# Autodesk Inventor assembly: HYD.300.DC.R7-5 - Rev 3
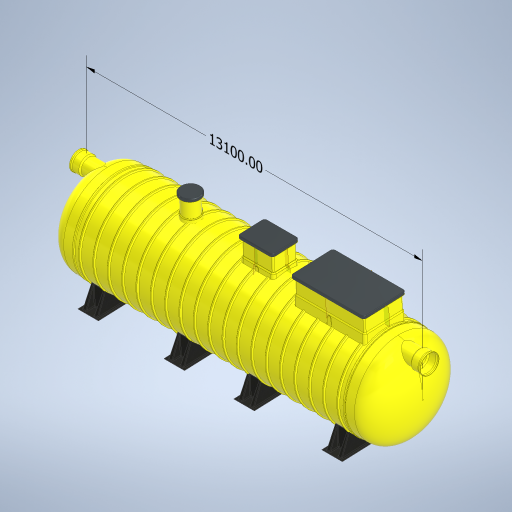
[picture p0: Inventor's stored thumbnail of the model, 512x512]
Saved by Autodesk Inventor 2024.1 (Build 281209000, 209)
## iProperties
Created: 2023-08
Part Number: HYD.300.DC.R7-5 - Rev 3
Document SubType Name: Assembly
Designer: macga
Author: macga
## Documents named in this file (47)
- D:\$ Protector Vault\Workspace\Automation Files\1. Protector Stardard Products\HydroProtectors\FAMILY\HYD.300 - Vernon\HYD.300.DC.R7-5 - Rev 3.iam
- D:\$ Protector Vault\Workspace\1. Protector Stardard Products\HydroProtectors\FAMILY\HORIZONTAL TANK - IPART\HORIZONTAL TANK - IPART.ipt
- D:\$ Protector Vault\Workspace\1. Protector Stardard Products\HydroProtectors\FAMILY\DOME - IPART\DOME - IPART.ipt
- D:\$ Protector Vault\Workspace\1. Protector Stardard Products\HydroProtectors\FAMILY\FOOT - IPART\FRP Foot - IPART.ipt
- D:\$ Protector Vault\Workspace\1. Protector Stardard Products\HydroProtectors\FAMILY\ACDTUBE - IPART\ACDTUBE - IPART.ipt
- D:\$ Protector Vault\Workspace\1. Protector Stardard Products\HydroProtectors\FAMILY\ACD FLOAT VALVE - IPART\ACD.FloatValve - IASSY.iam
- D:\$ Protector Vault\Workspace\1. Protector Stardard Products\HydroProtectors\FAMILY\OUTLET ELBOW - IPART\OUTLET ELBOW - IPART.ipt
- D:\$ Protector Vault\Workspace\1. Protector Stardard Products\HydroProtectors\Coalescer Guide Rail.ipt
- D:\$ Protector Vault\Workspace\1. Protector Stardard Products\HydroProtectors\Upper Guide Rai Braket.ipt
- D:\$ Protector Vault\Workspace\1. Protector Stardard Products\Standard Components\Flanged Vent.ipt
- D:\$ Protector Vault\Workspace\1. Protector Stardard Products\Xtremeprotector\Vault\Chain.ipt
- D:\$ Protector Vault\Workspace\1. Protector Stardard Products\Xtremeprotector\Vault\Lifting Eye.ipt
- D:\$ Protector Vault\Workspace\1. Protector Stardard Products\HydroProtectors\FAMILY\ACDTUBE - IPART\ACDTUBE - IPART\ACDTUBE.750-3300.ipt
- D:\$ Protector Vault\Workspace\1. Protector Stardard Products\HydroProtectors\FAMILY\ACD FLOAT VALVE - IPART\ACD.FloatValve - IASSY\ACD.FVALVE.750.ASSY.iam
- D:\$ Protector Vault\Workspace\1. Protector Stardard Products\HydroProtectors\FAMILY\SU.900X1200.ManwayRiserAdaptor - IPART\SU.900X1200.ManwayRiserAdapator - IPART.ipt
- D:\$ Protector Vault\Workspace\1. Protector Stardard Products\Standard Components\900x1200x600 Manway Riser.ipt
- D:\$ Protector Vault\Workspace\1. Protector Stardard Products\Standard Components\900x1200 Manway Cover ST\900x900 Manway Cover Class D ST-02.ipt
- D:\$ Protector Vault\Workspace\1. Protector Stardard Products\Standard Components\900x1200 Manway Cover ST.ipt
- D:\$ Protector Vault\Workspace\1. Protector Stardard Products\HydroProtectors\FAMILY\DOME - IPART\DOME - IPART\SU.DOME.3500-22.ipt
- D:\$ Protector Vault\Workspace\1. Protector Stardard Products\HydroProtectors\FAMILY\FOOT - IPART\FRP Foot - IPART\SU.HS.FOOT.3500.ipt
- D:\$ Protector Vault\Workspace\1. Protector Stardard Products\HydroProtectors\FAMILY\HYD.BAFFLE - IPART\SU.BAFFLE.3500\SU.BAFFLE.3500-1100x775x610.ipt
- D:\$ Protector Vault\Workspace\1. Protector Stardard Products\HydroProtectors\FAMILY\HYD.BAFFLE - IPART\SU.BAFFLE.3500.ipt
- D:\$ Protector Vault\Workspace\1. Protector Stardard Products\HydroProtectors\FAMILY\ACD Base - IPART\SU.ACDBASE.3500\SU.ACDBASE.3500-700,1100.ipt
- D:\$ Protector Vault\Workspace\1. Protector Stardard Products\HydroProtectors\FAMILY\ACD Base - IPART\SU.ACDBASE.3500.ipt
- D:\$ Protector Vault\Workspace\1. Protector Stardard Products\HydroProtectors\FAMILY\SU.900X1200.ManwayRiserAdaptor - IPART\SU.900X1200.ManwayRiserAdapator - IPART\SU.900x1200ManwayRiserAdapter.3500.ipt
- D:\$ Protector Vault\Workspace\1. Protector Stardard Products\HydroProtectors\FAMILY\Coalescer Guide Rail-0124.ipt
- D:\$ Protector Vault\Workspace\1. Protector Stardard Products\HydroProtectors\FAMILY\Coalescer Guide Rail-0125.ipt
- D:\$ Protector Vault\Workspace\1. Protector Stardard Products\HydroProtectors\FAMILY\CF.BASE - IPART\CF BASE PENTA  2.0 - IPART.ipt
- D:\$ Protector Vault\Workspace\1. Protector Stardard Products\Standard Components\1500x2700 Manway Adaptor\SU.1500x2700ManwayRiserAdaptor.3500.ipt
- D:\$ Protector Vault\Workspace\1. Protector Stardard Products\Standard Components\1500x2700 Manway Adaptor.ipt
- D:\$ Protector Vault\Workspace\1. Protector Stardard Products\Standard Components\1500x2700x600 Manway Riser.ipt
- D:\$ Protector Vault\Workspace\1. Protector Stardard Products\Standard Components\1500x2700 Manway Cover ST\1500x2700 Manway Cover Class D ST-02.ipt
- D:\$ Protector Vault\Workspace\1. Protector Stardard Products\Standard Components\1500x2700 Manway Cover ST.ipt
- D:\$ Protector Vault\Workspace\1. Protector Stardard Products\HydroProtectors\FAMILY\HORIZONTAL TANK - IPART\HORIZONTAL TANK - IPART\WIN.HB.3500x10600L-22.ipt
- D:\$ Protector Vault\Workspace\1. Protector Stardard Products\HydroProtectors\FAMILY\COALESCER FILTER - IPART\CF-R7.iam
- D:\$ Protector Vault\Workspace\1. Protector Stardard Products\Xtremeprotector\Vault\Chain\Chain-55.ipt
- D:\$ Protector Vault\Workspace\1. Protector Stardard Products\HydroProtectors\FAMILY\CF.BASE - IPART\CF BASE PENTA  2.0 - IPART\SU.CFBASE.3500.B2.5-R7-OP.450.ipt
- D:\$ Protector Vault\Workspace\1. Protector Stardard Products\HydroProtectors\FAMILY\COALESCER FILTER - IPART\CF-R7_MIR6.iam
- D:\$ Protector Vault\Workspace\1. Protector Stardard Products\Xtremeprotector\Vault\Lifting Eye_MIR12.ipt
- D:\$ Protector Vault\Workspace\1. Protector Stardard Products\HydroProtectors\Upper Guide Rai Braket_MIR12.ipt
- D:\$ Protector Vault\Workspace\1. Protector Stardard Products\600 Dia Adaptor, Riser, Cover Assy - 3500\600 Dia Adaptor, Riser, Class D Cover Assy -3000.iam
- D:\$ Protector Vault\Workspace\1. Protector Stardard Products\600 Dia Adaptor, Riser, Cover Assy - 3500.iam
- D:\$ Protector Vault\Workspace\1. Protector Stardard Products\StormProtector\600 Storm Pro Inlet Elbow.ipt
- D:\$ Protector Vault\Workspace\1. Protector Stardard Products\HydroProtectors\FAMILY\OUTLET ELBOW - IPART\OUTLET ELBOW - IPART\OutletPipeElbow.600D-100DCoupling.ipt
- D:\$ Protector Vault\Workspace\1. Protector Stardard Products\StormProtector\600 Storm Pro Pipe and Socket.ipt
- D:\$ Protector Vault\Workspace\1. Protector Stardard Products\StormProtector\ISO 4065 Pipe DN630x15.4xS20 - 3000.ipt
- D:\$ Protector Vault\Workspace\1. Protector Stardard Products\Trade Waste Sampling Point Assembly 600.iam
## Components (51 placed, 30 different names)
1. WIN.HB.3500x10600L-22:1
2. SU.DOME.3500-22:1 — Mate:1, Mate:3, Mate:78, Mate:93, Mate:176, Angle:5, Angle:11
3. 600 Storm Pro Inlet Elbow:1 — Mate:176, Angle:5, Tangent:135
4. SU.DOME.3500-22:2 — Mate:2, Mate:4, Mate:94, Mate:172
5. SU.HS.FOOT.3500:1 — Mate:74, Mate:75, Angle:7
6. SU.HS.FOOT.3500:2 — Mate:76, Mate:77, Angle:10
7. SU.HS.FOOT.3500:3 — Mate:149, Angle:9, Mate:232
8. SU.HS.FOOT.3500:4 — Mate:147, Mate:148, Angle:8
9. SU.BAFFLE.3500-1100x775x610:1
10. SU.ACDBASE.3500-700,1100:1
11. ACDTUBE.750-3300:1 — Mate:14, Mate:208
12. ACD.FVALVE.750.ASSY:1 [sub-assembly] — Mate:208
13. SU.CFBASE.3500.B2.5-R7-OP.450:1 — Mate:16, Flush:173, Mate:154, Mate:221, Mate:222, Mate:223, Mate:247, Mate:248
14. CF-R7:2 [sub-assembly] — Mate:86, Tangent:4
15. CF-R7:1 [sub-assembly] — Mate:154, Mate:157, Tangent:126
16. ISO 4065 Pipe DN630x15.4xS20 - 3000:1 — Mate:247, Mate:248, Mate:251, Mate:252
17. OutletPipeElbow.600D-100DCoupling:2 — Mate:249, Mate:250, Mate:251, Mate:252
18. 600 Storm Pro Pipe and Socket:1 — Mate:249, Mate:250, Mate:253, Mate:254
19. 900x1200x600 Manway Riser:1 — Mate:187, Mate:188, Mate:189
20. 900x900 Manway Cover Class D ST-02:1 — Flush:222
21. Flanged Vent:3 — Mate:194, Mate:195
22. Flanged Vent:4
23. SU.900x1200ManwayRiserAdapter.3500:1
24. Chain-55:1 — Mate:157, Tangent:126, Tangent:127
25. Chain-55:2 — Mate:86, Tangent:4, Tangent:128
26. Lifting Eye:1 — Tangent:127, Mate:160
27. Lifting Eye:2 — Tangent:128, Mate:161
28. Coalescer Guide Rail-0124:1 — Mate:62, Mate:63, Flush:5
29. Coalescer Guide Rail-0125:2 — Mate:64, Mate:65, Flush:6
30. Upper Guide Rai Braket:1 — Mate:62, Mate:63, Flush:5, Mate:160
31. Upper Guide Rai Braket:2 — Mate:64, Mate:65, Flush:6, Mate:161
32. SU.1500x2700ManwayRiserAdaptor.3500:1
33. 1500x2700x600 Manway Riser:1 — Mate:233, Mate:234, Mate:235
34. 1500x2700 Manway Cover Class D ST-02:1 — Angle:17
35. CF-R7:3 [sub-assembly] — Mate:236, Tangent:130
36. Coalescer Guide Rail-0124:5 — Mate:221, Mate:222, Mate:223
37. Upper Guide Rai Braket:3
38. Chain-55:3 — Tangent:129, Mate:236
39. Lifting Eye:3 — Tangent:129, Mate:233, Mate:234, Mate:235, Tangent:130
40. CF-R7_MIR6:1 [sub-assembly] — Tangent:134, Mate:244, Flush:221
41. CF-R7_MIR6:2 [sub-assembly] — Tangent:133, Mate:243, Flush:221
42. Chain-55:4 — Tangent:131, Tangent:133, Mate:243
43. Chain-55:5 — Tangent:132, Tangent:134, Mate:244
44. Lifting Eye_MIR12:1 — Tangent:131, Mate:241
45. Lifting Eye_MIR12:2 — Tangent:132, Mate:242
46. Coalescer Guide Rail-0124:6 — Flush:219, Mate:237, Mate:238
47. Coalescer Guide Rail-0125:7 — Flush:220, Mate:239, Mate:240
48. Upper Guide Rai Braket_MIR12:1 — Flush:219, Mate:237, Mate:238, Mate:241
49. Upper Guide Rai Braket_MIR12:2 — Flush:220, Mate:239, Mate:240, Mate:242
50. 600 Dia Adaptor, Riser, Class D Cover Assy -3000:1 [sub-assembly] — Mate:245, Flush:222, Mate:246
51. Trade Waste Sampling Point Assembly 600:1 [sub-assembly] — Mate:253, Angle:17, Mate:254
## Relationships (84: Mate 59, Tangent 11, Flush 7, Angle 7)
- Mate:1: SU.DOME.3500-22:1
- Mate:2: SU.DOME.3500-22:2
- Mate:3: SU.DOME.3500-22:1
- Mate:4: SU.DOME.3500-22:2
- Mate:14: ACDTUBE.750-3300:1
- Mate:16: SU.CFBASE.3500.B2.5-R7-OP.450:1
- Flush:173: SU.CFBASE.3500.B2.5-R7-OP.450:1
- Mate:62: Coalescer Guide Rail-0124:1 ↔ Upper Guide Rai Braket:1
- Mate:63: Coalescer Guide Rail-0124:1 ↔ Upper Guide Rai Braket:1
- Flush:5: Coalescer Guide Rail-0124:1 ↔ Upper Guide Rai Braket:1
- Mate:64: Coalescer Guide Rail-0125:2 ↔ Upper Guide Rai Braket:2
- Mate:65: Coalescer Guide Rail-0125:2 ↔ Upper Guide Rai Braket:2
- Flush:6: Coalescer Guide Rail-0125:2 ↔ Upper Guide Rai Braket:2
- Mate:74: SU.HS.FOOT.3500:1
- Mate:75: SU.HS.FOOT.3500:1
- Mate:76: SU.HS.FOOT.3500:2
- Mate:77: SU.HS.FOOT.3500:2
- Mate:78: SU.DOME.3500-22:1
- Mate:86: CF-R7:2 ↔ Chain-55:2
- Tangent:4: CF-R7:2 ↔ Chain-55:2
- Mate:93: SU.DOME.3500-22:1
- Mate:94: SU.DOME.3500-22:2
- Mate:208: ACDTUBE.750-3300:1 ↔ ACD.FVALVE.750.ASSY:1
- Mate:147: SU.HS.FOOT.3500:4
- Mate:148: SU.HS.FOOT.3500:4
- Mate:149: SU.HS.FOOT.3500:3
- Mate:176: SU.DOME.3500-22:1 ↔ 600 Storm Pro Inlet Elbow:1
- Angle:5: SU.DOME.3500-22:1 ↔ 600 Storm Pro Inlet Elbow:1
- Angle:7: SU.HS.FOOT.3500:1
- Angle:8: SU.HS.FOOT.3500:4
- Angle:9: SU.HS.FOOT.3500:3
- Angle:10: SU.HS.FOOT.3500:2
- Angle:11: SU.DOME.3500-22:1
- Mate:154: SU.CFBASE.3500.B2.5-R7-OP.450:1 ↔ CF-R7:1
- Mate:157: CF-R7:1 ↔ Chain-55:1
- Tangent:126: CF-R7:1 ↔ Chain-55:1
- Tangent:127: Chain-55:1 ↔ Lifting Eye:1
- Tangent:128: Chain-55:2 ↔ Lifting Eye:2
- Mate:160: Lifting Eye:1 ↔ Upper Guide Rai Braket:1
- Mate:161: Lifting Eye:2 ↔ Upper Guide Rai Braket:2
- Mate:172: SU.DOME.3500-22:2
- Mate:187: 900x1200x600 Manway Riser:1
- Mate:188: 900x1200x600 Manway Riser:1
- Mate:189: 900x1200x600 Manway Riser:1
- Mate:194: Flanged Vent:3
- Mate:195: Flanged Vent:3
- Mate:221: SU.CFBASE.3500.B2.5-R7-OP.450:1 ↔ Coalescer Guide Rail-0124:5
- Mate:222: SU.CFBASE.3500.B2.5-R7-OP.450:1 ↔ Coalescer Guide Rail-0124:5
- Mate:223: SU.CFBASE.3500.B2.5-R7-OP.450:1 ↔ Coalescer Guide Rail-0124:5
- Mate:232: SU.HS.FOOT.3500:3
- Tangent:129: Chain-55:3 ↔ Lifting Eye:3
- Mate:233: 1500x2700x600 Manway Riser:1 ↔ Lifting Eye:3
- Mate:234: 1500x2700x600 Manway Riser:1 ↔ Lifting Eye:3
- Mate:235: 1500x2700x600 Manway Riser:1 ↔ Lifting Eye:3
- Mate:236: CF-R7:3 ↔ Chain-55:3
- Tangent:130: CF-R7:3 ↔ Lifting Eye:3
- Flush:219: Coalescer Guide Rail-0124:6 ↔ Upper Guide Rai Braket_MIR12:1
- Mate:237: Coalescer Guide Rail-0124:6 ↔ Upper Guide Rai Braket_MIR12:1
- Mate:238: Coalescer Guide Rail-0124:6 ↔ Upper Guide Rai Braket_MIR12:1
- Flush:220: Coalescer Guide Rail-0125:7 ↔ Upper Guide Rai Braket_MIR12:2
- Mate:239: Coalescer Guide Rail-0125:7 ↔ Upper Guide Rai Braket_MIR12:2
- Mate:240: Coalescer Guide Rail-0125:7 ↔ Upper Guide Rai Braket_MIR12:2
- Tangent:131: Chain-55:4 ↔ Lifting Eye_MIR12:1
- Mate:241: Lifting Eye_MIR12:1 ↔ Upper Guide Rai Braket_MIR12:1
- Tangent:132: Chain-55:5 ↔ Lifting Eye_MIR12:2
- Mate:242: Lifting Eye_MIR12:2 ↔ Upper Guide Rai Braket_MIR12:2
- Tangent:133: CF-R7_MIR6:2 ↔ Chain-55:4
- Mate:243: CF-R7_MIR6:2 ↔ Chain-55:4
- Tangent:134: CF-R7_MIR6:1 ↔ Chain-55:5
- Mate:244: CF-R7_MIR6:1 ↔ Chain-55:5
- Flush:221: CF-R7_MIR6:1 ↔ CF-R7_MIR6:2
- Mate:245: 600 Dia Adaptor, Riser, Class D Cover Assy -3000:1
- Flush:222: 900x900 Manway Cover Class D ST-02:1 ↔ 600 Dia Adaptor, Riser, Class D Cover Assy -3000:1
- Mate:246: 600 Dia Adaptor, Riser, Class D Cover Assy -3000:1
- Mate:247: SU.CFBASE.3500.B2.5-R7-OP.450:1 ↔ ISO 4065 Pipe DN630x15.4xS20 - 3000:1
- Mate:248: SU.CFBASE.3500.B2.5-R7-OP.450:1 ↔ ISO 4065 Pipe DN630x15.4xS20 - 3000:1
- Mate:249: OutletPipeElbow.600D-100DCoupling:2 ↔ 600 Storm Pro Pipe and Socket:1
- Mate:250: OutletPipeElbow.600D-100DCoupling:2 ↔ 600 Storm Pro Pipe and Socket:1
- Mate:251: ISO 4065 Pipe DN630x15.4xS20 - 3000:1 ↔ OutletPipeElbow.600D-100DCoupling:2
- Mate:252: ISO 4065 Pipe DN630x15.4xS20 - 3000:1 ↔ OutletPipeElbow.600D-100DCoupling:2
- Tangent:135: 600 Storm Pro Inlet Elbow:1
- Mate:253: 600 Storm Pro Pipe and Socket:1 ↔ Trade Waste Sampling Point Assembly 600:1
- Angle:17: 1500x2700 Manway Cover Class D ST-02:1 ↔ Trade Waste Sampling Point Assembly 600:1
- Mate:254: 600 Storm Pro Pipe and Socket:1 ↔ Trade Waste Sampling Point Assembly 600:1
## Named parameters: d484_d77 = 35 mm, d485_d75 = 0, d486_d76 = 1 mm, d507_d341 = 0
